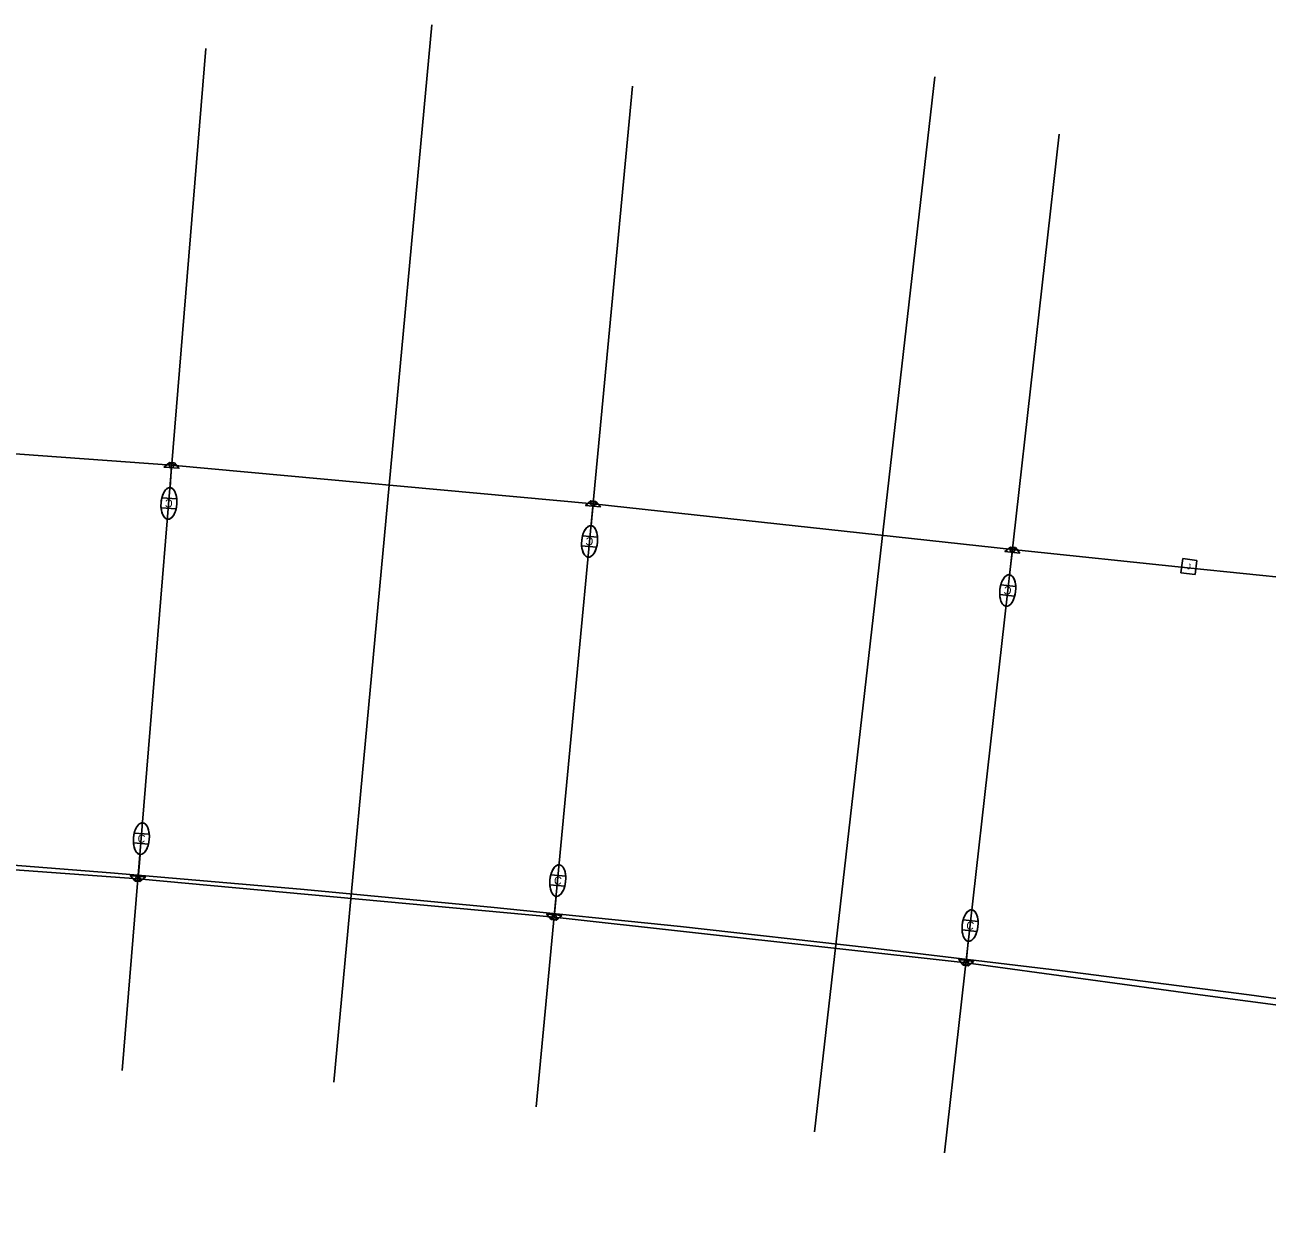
# Model space of a CAD drawing. Extents: x 915723 to 927758, y 636394 to 638609.
# Drawn here: x 924200 to 924821, y 636743 to 637335 of the extents above; entities that cross this region are included whole.
import ezdxf

# ---------------------------------------------------------------- set-up
doc = ezdxf.new("R2010")
doc.units = 0
for name, color, linetype in [('ConduitBM', 7, 'Continuous'), ('ConduitJB', 7, 'Continuous'), ('ConduitOT', 7, 'Continuous'), ('DrShaftConc', 7, 'Continuous'), ('Masonry_h', 7, 'Continuous'), ('Miscellaneous2', 7, 'Continuous'), ('PoleLight', 7, 'Continuous'), ('PullBox', 7, 'Continuous'), ('TextStructuresLabel', 7, 'Continuous')]:
    doc.layers.add(name, color=color, linetype=linetype)

msp = doc.modelspace()

# ---------------------------------------------------------------- linework, layer by layer
at = {"layer": 'ConduitBM'}
for p, q in [((924062.22, 637130.27), (924273.78, 637114.85)), ((924273.78, 637114.85), (924484.41, 637095.67)), ((924484.41, 637095.67), (924693.98, 637072.72)), ((924693.98, 637072.72), (924783.08, 637063.49)), ((924050.24, 636923.47), (924257, 636908.15)), ((924257, 636908.15), (924464.95, 636889.05)), ((924464.95, 636889.05), (924670.79, 636866.19)), ((924670.79, 636866.19), (924787.88, 636850.28)), ((924787.88, 636850.28), (924949.92, 636828.26))]:
    msp.add_line(p, q, dxfattribs=at)
at = {"layer": 'ConduitJB'}
msp.add_line((924783.08, 637063.49), (924983.84, 637042.69), dxfattribs=at)
at = {"layer": 'DrShaftConc'}
for p, q in [((924403.78, 637334.94), (924354.89, 636806.63)), ((924655.25, 637308.96), (924595.07, 636781.81))]:
    msp.add_line(p, q, dxfattribs=at)
msp.add_lwpolyline([(924148.09, 636918.61), (924243.21, 636911.23), (924338.26, 636903.05), (924433.24, 636894.08), (924528.14, 636884.3), (924622.95, 636873.74), (924717.68, 636862.37), (924812.3, 636850.22), (924906.82, 636837.27), (925001.23, 636823.53), (925095.52, 636808.99), (925147.31, 636800.67), (925147.31, 636800.67), (925499.92, 636743.14)], dxfattribs=at)
at = {"layer": 'Masonry_h'}
for p, q in [((924290.83, 637323.05), (924249.04, 636812.4)), ((924504.05, 637304.28), (924456.02, 636794.19)), ((924717.35, 637280.25), (924660.01, 636771.21))]:
    msp.add_line(p, q, dxfattribs=at)
at = {"layer": 'Miscellaneous2'}
for p, q in [((924276.35, 637098.02), (924268.86, 637098.56)), ((924268.86, 637098.56), (924268.86, 637098.56)), ((924268.5, 637093.57), (924268.5, 637093.57)), ((924268.5, 637093.57), (924276, 637093.04)), ((924486.63, 637078.96), (924479.15, 637079.66)), ((924479.15, 637079.66), (924479.15, 637079.66)), ((924478.69, 637074.68), (924478.69, 637074.68)), ((924478.69, 637074.68), (924486.17, 637073.99)), ((924695.66, 637054.34), (924688.2, 637055.19)), ((924688.2, 637055.19), (924688.2, 637055.19)), ((924687.63, 637050.23), (924687.63, 637050.23)), ((924687.63, 637050.23), (924695.1, 637049.37)), ((924262.6, 636930.49), (924255.11, 636931.1)), ((924254.7, 636926.12), (924262.19, 636925.51)), ((924262.19, 636925.51), (924262.19, 636925.51)), ((924262.6, 636930.49), (924262.6, 636930.49)), ((924470.74, 636909.45), (924463.26, 636910.19)), ((924470.74, 636909.45), (924470.74, 636909.45)), ((924462.77, 636905.21), (924470.25, 636904.48)), ((924470.25, 636904.48), (924470.25, 636904.48)), ((924676.84, 636886.88), (924669.37, 636887.74)), ((924668.8, 636882.77), (924676.27, 636881.92)), ((924676.27, 636881.92), (924676.27, 636881.92)), ((924676.84, 636886.88), (924676.84, 636886.88))]:
    msp.add_line(p, q, dxfattribs=at)
for centre, major_axis, start_param, end_param in [((924272.43, 637095.8), (0.56, 7.9), 1.249648, 1.891946), ((924272.43, 637095.8), (0.56, 7.9), 4.391271, 5.033538), ((924272.43, 637095.8), (0.56, 7.9), 4.391241, 4.391271), ((924482.66, 637076.82), (0.73, 7.89), 1.249648, 1.891946), ((924482.66, 637076.82), (0.73, 7.89), 4.391271, 5.033538), ((924482.66, 637076.82), (0.73, 7.89), 4.391241, 4.391271), ((924691.65, 637052.28), (0.9, 7.87), 1.249648, 1.891946), ((924691.65, 637052.28), (0.9, 7.87), 4.391271, 5.033538), ((924691.65, 637052.28), (0.9, 7.87), 4.391241, 4.391271), ((924258.65, 636928.3), (-0.65, -7.89), 4.391271, 5.033538), ((924258.65, 636928.3), (-0.65, -7.89), 4.391241, 4.391271), ((924258.65, 636928.3), (-0.65, -7.89), 1.249648, 1.891946), ((924466.76, 636907.33), (-0.78, -7.88), 4.391271, 5.033538), ((924466.76, 636907.33), (-0.78, -7.88), 4.391241, 4.391271), ((924466.76, 636907.33), (-0.78, -7.88), 1.249648, 1.891946), ((924672.82, 636884.83), (-0.9, -7.87), 4.391271, 5.033538), ((924672.82, 636884.83), (-0.9, -7.87), 4.391241, 4.391271), ((924672.82, 636884.83), (-0.9, -7.87), 1.249648, 1.891946)]:
    msp.add_ellipse(centre, major_axis=major_axis, ratio=0.5, start_param=start_param, end_param=end_param, dxfattribs=at)
at = {"layer": 'PoleLight'}
for p, q in [((924273.78, 637114.85), (924272.99, 637103.7)), ((924268.86, 637098.56), (924276.35, 637098.02)), ((924276, 637093.04), (924268.5, 637093.57)), ((924484.4, 637095.58), (924483.39, 637084.71)), ((924479.15, 637079.66), (924486.63, 637078.96)), ((924486.17, 637073.99), (924478.69, 637074.68)), ((924693.95, 637072.42), (924692.54, 637060.15)), ((924688.2, 637055.19), (924695.66, 637054.34)), ((924695.1, 637049.37), (924687.63, 637050.23)), ((924255.11, 636931.1), (924262.6, 636930.49)), ((924262.19, 636925.51), (924254.7, 636926.12)), ((924257, 636908.15), (924258.01, 636920.41)), ((924463.26, 636910.19), (924470.74, 636909.45)), ((924470.25, 636904.48), (924462.77, 636905.21)), ((924464.95, 636889.05), (924465.98, 636899.45)), ((924669.37, 636887.74), (924676.84, 636886.88)), ((924676.27, 636881.92), (924668.8, 636882.77)), ((924670.79, 636866.19), (924671.92, 636876.96))]:
    msp.add_line(p, q, dxfattribs=at)
for points in [[(924275.18, 637116.04), (924272.68, 637116.24), (924269.99, 637113.96), (924277.46, 637113.34)], [(924485.84, 637096.8), (924483.35, 637097.05), (924480.62, 637094.81), (924488.08, 637094.07)], [(924695.45, 637073.73), (924692.97, 637074.01), (924690.19, 637071.83), (924697.64, 637070.96)], [(924255.48, 636907.05), (924257.97, 636906.85), (924260.67, 636909.12), (924253.19, 636909.74)], [(924463.51, 636887.85), (924465.99, 636887.61), (924468.73, 636889.83), (924461.27, 636890.59)], [(924669.33, 636865.09), (924671.81, 636864.8), (924674.59, 636866.97), (924667.14, 636867.87)]]:
    msp.add_lwpolyline(points, close=True, dxfattribs=at)
for centre in [(924273.78, 637114.85), (924484.41, 637095.66), (924693.99, 637072.61), (924256.9, 636908.2), (924464.95, 636888.98), (924670.79, 636866.19)]:
    msp.add_circle(centre, 1.14, dxfattribs=at)
for centre, major_axis in [((924272.43, 637095.8), (0.56, 7.9)), ((924482.66, 637076.82), (0.73, 7.89)), ((924691.65, 637052.28), (0.9, 7.87)), ((924258.65, 636928.3), (-0.65, -7.89)), ((924466.76, 636907.33), (-0.78, -7.88)), ((924672.82, 636884.83), (-0.9, -7.87))]:
    msp.add_ellipse(centre, major_axis=major_axis, ratio=0.5, dxfattribs=at)
for centre, major_axis, start_param, end_param in [((924272.43, 637095.8), (0.56, 7.9), 0.847605, 1.249648), ((924272.43, 637095.8), (0.56, 7.9), 0, 0.847605), ((924272.43, 637095.8), (0.56, 7.9), 5.033538, 6.283185), ((924272.43, 637095.8), (0.56, 7.9), 1.891945, 4.391241), ((924482.66, 637076.82), (0.73, 7.89), 0.847605, 1.249648), ((924482.66, 637076.82), (0.73, 7.89), 0, 0.847605), ((924482.66, 637076.82), (0.73, 7.89), 5.033538, 6.283185), ((924482.66, 637076.82), (0.73, 7.89), 1.891945, 4.391241), ((924691.65, 637052.28), (0.9, 7.87), 0.847605, 1.249648), ((924691.65, 637052.28), (0.9, 7.87), 0, 0.847605), ((924691.65, 637052.28), (0.9, 7.87), 5.033538, 6.283185), ((924691.65, 637052.28), (0.9, 7.87), 1.891945, 4.391241), ((924258.65, 636928.3), (-0.65, -7.89), 1.891945, 4.391241), ((924258.65, 636928.3), (-0.65, -7.89), 5.033538, 6.283185), ((924258.65, 636928.3), (-0.65, -7.89), 0.847605, 1.249648), ((924258.65, 636928.3), (-0.65, -7.89), 0, 0.847605), ((924466.76, 636907.33), (-0.78, -7.88), 1.891945, 4.391241), ((924466.76, 636907.33), (-0.78, -7.88), 5.033538, 6.283185), ((924466.76, 636907.33), (-0.78, -7.88), 0, 0.847605), ((924466.76, 636907.33), (-0.78, -7.88), 0.847605, 1.249648), ((924672.82, 636884.83), (-0.9, -7.87), 1.891945, 4.391241), ((924672.82, 636884.83), (-0.9, -7.87), 5.033538, 6.283185), ((924672.82, 636884.83), (-0.9, -7.87), 0.847605, 1.249648), ((924672.82, 636884.83), (-0.9, -7.87), 0, 0.847605)]:
    msp.add_ellipse(centre, major_axis=major_axis, ratio=0.5, start_param=start_param, end_param=end_param, dxfattribs=at)
at = {"layer": 'PullBox'}
for p, q in [((924778.21, 637061.17), (924779.13, 637068.24)), ((924779.13, 637068.24), (924786.2, 637067.32)), ((924786.2, 637067.32), (924785.28, 637060.25)), ((924785.28, 637060.25), (924778.21, 637061.17))]:
    msp.add_line(p, q, dxfattribs=at)

# ---------------------------------------------------------------- texts
at = {"layer": 'ConduitOT'}
msp.add_text('J', height=2.85, rotation=352.57842, dxfattribs=at).set_placement((924781.06, 637062.96))
at = {"layer": 'TextStructuresLabel'}
for rotation, p in [(175.93959, (924274.44, 637097.66)), (174.71331, (924484.71, 637078.64)), (173.48703, (924693.73, 637054.06)), (355.3216, (924256.62, 636926.46)), (354.36004, (924464.7, 636905.53)), (353.48703, (924670.73, 636883.05))]:
    msp.add_text('C', height=4, rotation=rotation, dxfattribs=at).set_placement(p)

doc.saveas('drawing.dxf')
